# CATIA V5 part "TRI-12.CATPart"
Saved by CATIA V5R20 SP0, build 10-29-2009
Part number: _TRI-12
Definition: NONE
Nomenclature: _TRI-12
Source: Unknown
Description: PART-_TRI-12-DESC
Bounding box of the stored display mesh (mm): x 0 to 17.5, y -6 to 6, z -6 to 6
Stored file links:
  C:\Users\Utente\Desktop\IO LAVORO\3D X SITO CF\X SITO\PLASTICA\TRI\TRI-12.CATPart
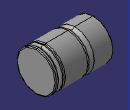
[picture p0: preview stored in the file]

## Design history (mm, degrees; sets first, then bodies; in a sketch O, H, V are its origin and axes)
Body1 "_TRI-12" (main body)
  Solid1: solid without history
